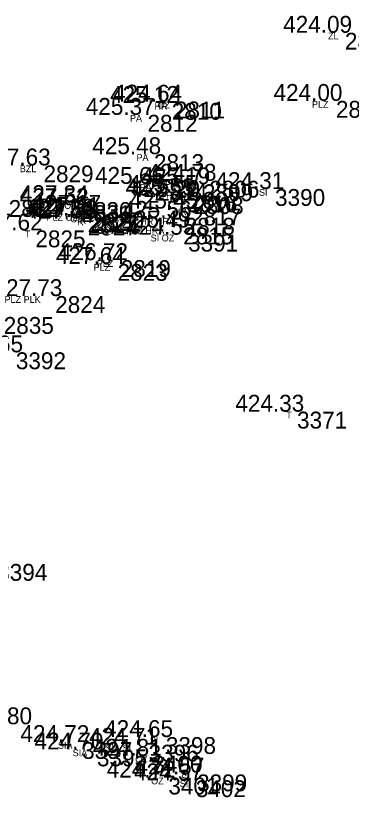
# Model space of a CAD drawing. Extents: x -639390 to -639075, y -1138747 to -1138358.
# Drawn here: x -639315.18 to -639300.23, y -1138401.22 to -1138366.46 of the extents above; entities that cross this region are included whole.
import ezdxf

# ---------------------------------------------------------------- set-up
doc = ezdxf.new("R2010")
doc.units = 0
for name, color, linetype in [('Vrstva 11', 7, 'Continuous'), ('Vrstva 12', 7, 'Continuous'), ('Vrstva 13', 7, 'Continuous'), ('Vrstva 57', 7, 'Continuous')]:
    doc.layers.add(name, color=color, linetype=linetype)

msp = doc.modelspace()

# ---------------------------------------------------------------- linework, layer by layer
at = {"layer": 'Vrstva 11'}
for p, q in [((-639300.8, -1138367.22), (-639300.8, -1138367.22)), ((-639308.51, -1138370.34), (-639308.51, -1138370.34)), ((-639308.37, -1138370.28), (-639308.37, -1138370.28)), ((-639301.2, -1138370.25), (-639301.2, -1138370.25)), ((-639309.59, -1138370.87), (-639309.59, -1138370.87)), ((-639309.3, -1138372.62), (-639309.3, -1138372.62)), ((-639314.22, -1138373.12), (-639314.22, -1138373.12)), ((-639309.16, -1138373.94), (-639309.16, -1138373.94)), ((-639306.84, -1138373.8), (-639306.84, -1138373.8)), ((-639307.69, -1138374.3), (-639307.69, -1138374.3)), ((-639307.12, -1138373.96), (-639307.12, -1138373.96)), ((-639303.91, -1138374.17), (-639303.91, -1138374.17)), ((-639307.82, -1138374.45), (-639307.82, -1138374.45)), ((-639307.54, -1138374.53), (-639307.54, -1138374.53)), ((-639312.53, -1138374.75), (-639312.53, -1138374.75)), ((-639312.53, -1138374.89), (-639312.53, -1138374.89)), ((-639312.12, -1138375.28), (-639312.12, -1138375.28)), ((-639311.97, -1138375.18), (-639311.97, -1138375.18)), ((-639307.65, -1138375.04), (-639307.65, -1138375.04)), ((-639312.26, -1138375.35), (-639312.26, -1138375.35)), ((-639312.25, -1138375.48), (-639312.25, -1138375.48)), ((-639312.14, -1138375.42), (-639312.14, -1138375.42)), ((-639307.93, -1138375.45), (-639307.93, -1138375.45)), ((-639314.58, -1138376.01), (-639314.58, -1138376.01)), ((-639308, -1138375.88), (-639308, -1138375.88)), ((-639307.78, -1138376.2), (-639307.78, -1138376.2)), ((-639310.78, -1138377.33), (-639310.78, -1138377.33)), ((-639310.92, -1138377.5), (-639310.92, -1138377.5)), ((-639313.7, -1138378.93), (-639313.7, -1138378.93)), ((-639302.93, -1138384.07), (-639302.93, -1138384.07)), ((-639308.77, -1138398.54), (-639308.77, -1138398.54)), ((-639312.5, -1138398.76), (-639312.5, -1138398.76)), ((-639309.54, -1138398.88), (-639309.54, -1138398.88)), ((-639311.84, -1138399.09), (-639311.84, -1138399.09)), ((-639309.37, -1138399.37), (-639309.37, -1138399.37)), ((-639308.66, -1138400.34), (-639308.66, -1138400.34)), ((-639307.38, -1138400.2), (-639307.38, -1138400.2)), ((-639307.44, -1138400.46), (-639307.44, -1138400.46))]:
    msp.add_line(p, q, dxfattribs=at)

# ---------------------------------------------------------------- texts
at = {"layer": 'Vrstva 12'}
for s, p in [('424.09 ', (-639303.269, -1138367.22)), ('425.12 ', (-639310.979, -1138370.34)), ('424.64 ', (-639310.839, -1138370.28)), ('424.00 ', (-639303.699, -1138370.25)), ('425.37 ', (-639312.059, -1138370.87)), ('425.48 ', (-639311.769, -1138372.62)), ('427.63 ', (-639316.689, -1138373.12)), ('425.66 ', (-639311.646, -1138373.94)), ('425.19 ', (-639309.589, -1138373.96)), ('424.78 ', (-639309.309, -1138373.8)), ('425.55 ', (-639310.16, -1138374.3)), ('424.31 ', (-639306.285, -1138374.17)), ('425.53 ', (-639310.289, -1138374.45)), ('425.20 ', (-639310.039, -1138374.53)), ('427.34 ', (-639314.999, -1138374.75)), ('427.52 ', (-639314.999, -1138374.89)), ('425.45 ', (-639310.12, -1138375.04)), ('427.36 ', (-639314.746, -1138375.35)), ('427.21 ', (-639314.495, -1138375.28)), ('427.17 ', (-639314.439, -1138375.18)), ('427.54 ', (-639314.719, -1138375.48)), ('427.58 ', (-639314.609, -1138375.42)), ('425.56 ', (-639310.416, -1138375.45)), ('427.62 ', (-639317.049, -1138376.01)), ('425.49 ', (-639310.469, -1138375.88)), ('424.55 ', (-639310.25, -1138376.2)), ('426.72 ', (-639313.249, -1138377.33)), ('427.64 ', (-639313.389, -1138377.5)), ('427.73 ', (-639316.169, -1138378.93)), ('424.65 ', (-639317.92, -1138381.43)), ('424.33 ', (-639305.399, -1138384.07)), ('424.65 ', (-639311.24, -1138398.54)), ('424.72 ', (-639314.969, -1138398.76)), ('424.71 ', (-639311.915, -1138398.88)), ('424.70 ', (-639314.339, -1138399.09)), ('424.81 ', (-639311.745, -1138399.37)), ('424.72 ', (-639311.129, -1138400.34)), ('424.57 ', (-639309.849, -1138400.2)), ('424.57 ', (-639309.909, -1138400.46))]:
    msp.add_text(s, height=0.75, dxfattribs=at).set_placement(p)
at = {"layer": 'Vrstva 13'}
for s, p in [(' 2804', (-639300.8, -1138367.97)), (' 2810', (-639308.51, -1138371.09)), (' 2811', (-639308.37, -1138371.03)), (' 2805', (-639301.2, -1138371)), (' 2812', (-639309.59, -1138371.62)), (' 2813', (-639309.3, -1138373.37)), (' 2829', (-639314.22, -1138373.87)), (' 2814', (-639309.16, -1138374.69)), (' 2809', (-639307.12, -1138374.71)), (' 2806', (-639306.84, -1138374.55)), (' 2807', (-639307.69, -1138375.05)), (' 3390', (-639303.91, -1138374.92)), (' 2832', (-639315.77, -1138375.41)), (' 2816', (-639307.82, -1138375.2)), (' 2808', (-639307.54, -1138375.28)), (' 2830', (-639312.53, -1138375.5)), (' 2831', (-639312.53, -1138375.64)), (' 2822', (-639312.26, -1138376.1)), (' 2821', (-639312.12, -1138376.03)), (' 2820', (-639311.97, -1138375.93)), (' 2817', (-639307.65, -1138375.79)), (' 2827', (-639312.25, -1138376.23)), (' 2826', (-639312.14, -1138376.17)), (' 2818', (-639307.93, -1138376.2)), (' 2825', (-639314.58, -1138376.76)), (' 2815', (-639308, -1138376.63)), (' 3391', (-639307.78, -1138376.95)), (' 2819', (-639310.78, -1138378.08)), (' 2823', (-639310.92, -1138378.25)), (' 2824', (-639313.7, -1138379.68)), (' 2835', (-639315.99, -1138380.61)), (' 3392', (-639315.45, -1138382.18)), (' 3371', (-639302.93, -1138384.82)), (' 3394', (-639316.28, -1138391.59)), (' 2680', (-639316.96, -1138397.97)), (' 3398', (-639308.77, -1138399.29)), (' 3397', (-639312.5, -1138399.51)), (' 3396', (-639309.54, -1138399.63)), (' 3395', (-639311.84, -1138399.84)), (' 3400', (-639309.37, -1138400.12)), (' 3401', (-639308.66, -1138401.09)), (' 3399', (-639307.38, -1138400.95)), (' 3402', (-639307.44, -1138401.21))]:
    msp.add_text(s, height=0.75, dxfattribs=at).set_placement(p)
at = {"layer": 'Vrstva 57'}
for s, p in [('ZL', (-639301.275, -1138367.52)), ('HR', (-639308.999, -1138370.64)), ('OZ', (-639308.859, -1138370.58)), ('PLZ', (-639301.989, -1138370.55)), ('PA', (-639310.09, -1138371.17)), ('PA', (-639309.8, -1138372.92)), ('BZL', (-639314.995, -1138373.42)), ('PA', (-639309.66, -1138374.24)), ('PLZ OZ', (-639308.529, -1138374.1)), ('PLZ', (-639308.479, -1138374.6)), ('HR', (-639307.609, -1138374.26)), ('SI', (-639304.348, -1138374.47)), ('PLZ', (-639308.329, -1138374.83)), ('HR', (-639308.309, -1138374.75)), ('OZ', (-639313.019, -1138375.05)), ('K', (-639312.705, -1138375.19)), ('PLZ OZ', (-639313.809, -1138375.58)), ('PLZ', (-639312.759, -1138375.48)), ('HR', (-639308.139, -1138375.34)), ('OZ', (-639312.749, -1138375.65)), ('K', (-639312.425, -1138375.78)), ('K', (-639312.315, -1138375.72)), ('HR HRA', (-639309.63, -1138375.75)), ('T', (-639314.78, -1138376.31)), ('PA PLZ HRA', (-639310.9, -1138376.18)), ('SI OZ', (-639309.169, -1138376.5)), ('PLZ', (-639311.569, -1138377.63)), ('PLZ', (-639311.709, -1138377.8)), ('PLZ PLK', (-639315.675, -1138379.23)), ('T', (-639303.13, -1138384.37)), ('SI', (-639309.208, -1138398.84)), ('SIA', (-639313.3, -1138399.06)), ('SIA SI', (-639311.178, -1138399.18)), ('SIA', (-639312.64, -1138399.39)), ('OZ', (-639309.859, -1138399.67)), ('OZ', (-639309.149, -1138400.64)), ('SI', (-639307.818, -1138400.5)), ('SI', (-639307.878, -1138400.76))]:
    msp.add_text(s, height=0.3, dxfattribs=at).set_placement(p)

doc.saveas('drawing.dxf')
